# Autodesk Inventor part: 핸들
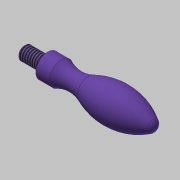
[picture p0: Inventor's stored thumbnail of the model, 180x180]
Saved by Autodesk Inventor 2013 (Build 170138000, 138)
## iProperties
Created: 2019-10
Part Number: 핸들
Material: 스테인리스강
Document SubType Name: Modeling
Designer: mduedu
Density: 1 g/cm^3
Author: mduedu
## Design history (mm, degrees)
sketch "스케치1"
  geometry: L1 (0, 0)-(0, 2); L2 (0, 2)-(7, 2); L3 (7, 2)-(7, 3.5); L4 (7, 3.5)-(11, 3.5); L5 (0, 0)-(39, 0); A1 r 9.5 centre (15.243, 12) between (11, 3.5) and (19.07, 3.305); A2 r 20 centre (27.128, -15) between (38.049, 1.754) and (19.07, 3.305); A3 r 2.094 centre (36.906, 0) between (39, 0) and (38.049, 1.754)
  constraints: 10 end point, 6 point on circle, 3 centre point, 3 parallel, 2 tangent, 1 perpendicular, 1 point on line, 1 vertical
  dimensions: "d0" = 39 distance of L1.start L5.end; "d1" = 4 diameter of L2 L5; "d2" = 7 diameter of L4 L5; "d3" = 7 distance of L1.end L2.end; "d4" = 4 distance of L3.end L4.end; "d5" = 5 dimension on A1 L5; "d6" = 9.5 radius of A1; "d7" = 10 dimension on A2 L5; "d8" = 20 radius of A2
revolve "회전1" sketch "스케치1" stored, may be unused: angle "d9" = 90 deg
feature "스레드1" dims "d10" = 6, "d11" = 0
chamfer "모따기1" distance "d12" = 0.5; stored, may be unused: second distance "d13" = 2, angle "d14" = 45 deg
node "솔리드1"
